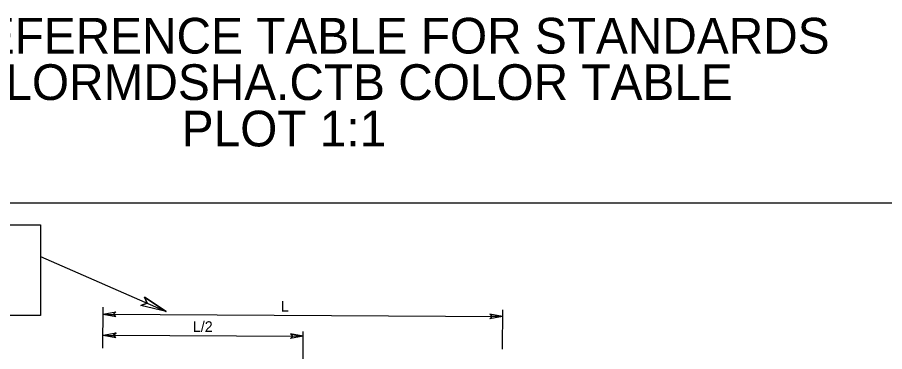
# Model space of a CAD drawing. Extents: x -0.5 to 21.6, y 4.3 to 17.8.
# Drawn here: x 2.452 to 7.307, y 15.456 to 17.329 of the extents above; entities that cross this region are included whole.
import ezdxf

# ---------------------------------------------------------------- set-up
doc = ezdxf.new("R2010")
doc.units = 0
for name, color, linetype in [('DETL-DIMS', 7, 'Continuous'), ('DETL-LINE', 7, 'Continuous'), ('DETL-NOTE', 7, 'Continuous'), ('TTLB-TEXT', 7, 'Continuous'), ('USER-BORD', 7, 'Continuous')]:
    doc.layers.add(name, color=color, linetype=linetype)

msp = doc.modelspace()

# ---------------------------------------------------------------- linework, layer by layer
at = {"layer": 'DETL-DIMS'}
for p, q in [((2.5807, 15.9885), (3.284, 15.6805)), ((3.284, 15.6805), (3.1632, 15.7609)), ((3.1632, 15.7609), (3.1778, 15.7271)), ((2.9303, 15.4751), (2.9317, 15.7053)), ((3.1778, 15.7271), (3.143, 15.7147)), ((3.284, 15.6805), (3.143, 15.7147)), ((5.1671, 15.4696), (5.1684, 15.6913)), ((2.9318, 15.6664), (3.0034, 15.6786)), ((2.9318, 15.6664), (3.0032, 15.6534)), ((2.9318, 15.6664), (5.1682, 15.6528)), ((2.9898, 15.666), (3.0034, 15.6786)), ((3.0032, 15.6534), (2.9898, 15.666)), ((5.1102, 15.6532), (5.0966, 15.6406)), ((5.1682, 15.6528), (5.0966, 15.6406)), ((5.1682, 15.6528), (5.0968, 15.6658)), ((5.0968, 15.6658), (5.1102, 15.6532)), ((2.9324, 15.5491), (3.004, 15.5613)), ((2.9324, 15.5491), (4.0518, 15.5424)), ((2.9324, 15.5491), (3.0038, 15.5361)), ((2.9904, 15.5488), (3.004, 15.5613)), ((3.0038, 15.5361), (2.9904, 15.5488)), ((3.9938, 15.5427), (3.9802, 15.5302)), ((4.0518, 15.5424), (3.9802, 15.5302)), ((4.0518, 15.5424), (3.9804, 15.5554)), ((3.9804, 15.5554), (3.9938, 15.5427)), ((4.0522, 15.0949), (4.0522, 15.5697))]:
    msp.add_line(p, q, dxfattribs=at)
for points in [[(0.509, 16.1657), (2.5807, 16.1657), (2.5807, 15.6587), (0.509, 15.6587)], [(3.1632, 15.7609), (3.284, 15.6805), (3.143, 15.7147), (3.1778, 15.7271)], [(3.0032, 15.6534), (2.9318, 15.6664), (3.0034, 15.6786), (2.9898, 15.666)], [(5.0968, 15.6658), (5.1682, 15.6528), (5.0966, 15.6406), (5.1102, 15.6532)], [(3.0038, 15.5361), (2.9324, 15.5491), (3.004, 15.5613), (2.9904, 15.5488)], [(3.9804, 15.5554), (4.0518, 15.5424), (3.9802, 15.5302), (3.9938, 15.5427)]]:
    msp.add_lwpolyline(points, close=True, dxfattribs=at)
at = {"layer": 'DETL-LINE'}
msp.add_lwpolyline([(0.3943, 14.1527), (0.3943, 16.2906), (7.7685, 16.2906), (7.7685, 5.9375), (0.3943, 5.9375), (0.3943, 13.6862)], dxfattribs=at)
at = {"layer": 'TTLB-TEXT'}
msp.add_line((0.3943, 16.2906), (7.7685, 16.2906), dxfattribs=at)
msp.add_lwpolyline([(0.3943, 16.2906), (7.7685, 16.2906), (7.7685, 5.9375), (0.3943, 5.9375)], close=True, dxfattribs=at)
at = {"layer": 'USER-BORD'}
msp.add_line((0.3943, 16.2906), (7.7685, 16.2906), dxfattribs=at)

# ---------------------------------------------------------------- texts
at = {"layer": 'DETL-LINE'}
for s, p in [('SAMPLE PREFERENCE TABLE FOR STANDARDS', (0.727, 17.126)), ('ATTACH CLORMDSHA.CTB COLOR TABLE', (1.0473, 16.866)), ('PLOT 1:1', (3.3719, 16.606))]:
    msp.add_text(s, height=0.2, dxfattribs=at).set_placement(p)
at = {"layer": 'DETL-NOTE'}
for s, p in [('L', (3.9267, 15.6803)), ('L/2', (3.4338, 15.5664))]:
    msp.add_text(s, height=0.06, dxfattribs=at).set_placement(p)

doc.saveas('drawing.dxf')
